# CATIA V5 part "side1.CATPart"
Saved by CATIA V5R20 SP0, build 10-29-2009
Part number: side1
Bounding box of the stored display mesh (mm): x 0 to 18, y 176.777 to 536.776, z -255.116 to 255.116
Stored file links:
  C:\Users\Dell\Desktop\Documentations\week8 doc\side1.CATPart
  C:\Users\Dell\Desktop\Documentations\week8 doc\Part1.CATPart
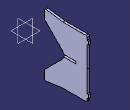
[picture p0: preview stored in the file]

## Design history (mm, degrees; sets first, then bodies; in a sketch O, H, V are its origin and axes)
Body1 (main body)
  DatumCurve1 to DatumCurve6
  DatumSurface1
  DatumCurve7
  DatumSurface2
  Sketch1 on yz-plane, origin (0, 0, 0), H (0, 1, 0), V (0, 0, 1)
    construction line L1 through (0, 141.421) direction (0, 1)
    construction line L2 through (0, 0) direction (1, 0)
    construction line L3 (0, 176.7765) -> (474.2497, 176.7765)
    point P1 (0, 176.7765)
    point P2 (474.2497, 176.7765)
    point P3 (70.8142, 0)
    point P4 (76.4276, 5.6156)
    line L4 (176.7765, 180.9186) -> (176.7765, 245.2199)
    point P5 (176.7765, 176.7765)
    point P6 (176.7765, 256.7765)
    line L5 (179.7054, 173.8476) -> (318.1319, 35.4211)
    arc A1 centre (282.7765, 0.0658) radius 50 from (331.9719, 9) to (318.1319, 35.4211) ccw
    point P7 (318.1319, 35.4211)
    line L6 (188.2132, 255.1162) -> (326.7765, 235)
    point P9 (326.7765, 235)
    point P10 (0, 332.8427)
    point P11 (673.0932, 332.8427)
    line L7 (326.7765, 235) -> (516.7765, 235)
    point P12 (526.7765, 235)
    line L8 (526.7765, 225) -> (526.7765, 205)
    point P13 (526.7765, 0)
    point P14 (332.7765, 0)
    line L9 (526.7765, 205) -> (536.7765, 205)
    point P15 (526.7765, 205)
    point P16 (536.7765, 205)
    line L10 (536.7765, 205) -> (536.7765, 175)
    point P17 (536.7765, 175)
    line L11 (536.7765, 175) -> (526.7765, 175)
    line L12 (526.7765, 175) -> (526.7765, 0)
    point P18 (526.7765, 175)
    line L13 (331.9719, 9) -> (432.7765, 9)
    point P19 (331.9719, 9)
    point P20 (432.7765, 9)
    line L14 (432.7765, 9) -> (432.7765, 0)
    point P21 (432.7765, 0)
    point P22 (0, 0)
    construction line L15 through (0, 0) direction (1, 0)
    construction line L16 through (0, 0) direction (0, -1)
    point P23 (474.2497, -176.7765)
    point P24 (0, -176.7765)
    construction line L17 (0, -176.7765) -> (474.2497, -176.7765)
    point P25 (70.8142, 0)
    point P26 (76.4276, -5.6156)
    point P27 (318.1319, -35.4211)
    point P29 (326.7765, -235)
    point P30 (673.0932, -332.8427)
    point P31 (0, -332.8427)
    construction line L18 (0, -332.8427) -> (673.0932, -332.8427)
    point P32 (526.7765, 0)
    point P33 (332.7765, 0)
    point P34 (526.7765, -205)
    point P35 (536.7765, -205)
    point P36 (536.7765, -175)
    point P37 (526.7765, -175)
    point P38 (331.9719, -9)
    point P39 (432.7765, -9)
    point P40 (432.7765, 0)
    line L19 (176.7765, -180.9186) -> (176.7765, -245.2199)
    line L20 (179.7054, -173.8476) -> (318.1319, -35.4211)
    arc A2 centre (282.7765, -0.0658) radius 50 from (331.9719, -9) to (318.1319, -35.4211) cw
    line L21 (188.2132, -255.1162) -> (326.7765, -235)
    line L22 (326.7765, -235) -> (516.7765, -235)
    line L23 (526.7765, -225) -> (526.7765, -205)
    line L24 (526.7765, -205) -> (536.7765, -205)
    line L25 (536.7765, -205) -> (536.7765, -175)
    line L26 (536.7765, -175) -> (526.7765, -175)
    line L27 (526.7765, -175) -> (526.7765, 0)
    line L28 (331.9719, -9) -> (432.7765, -9)
    line L29 (432.7765, -9) -> (432.7765, 0)
    construction line L30 (0, 474.8557) -> (0, -436.5473)
    point P41 (0, 474.8557)
    arc A3 centre (186.7765, 245.2199) radius 10 from (188.2132, 255.1162) to (176.7765, 245.2199) ccw
    point P43 (188.2132, 255.1162)
    point P44 (176.7765, 245.2199)
    arc A4 centre (516.7765, 225) radius 10 from (516.7765, 235) to (526.7765, 225) cw
    point P46 (516.7765, 235)
    point P47 (526.7765, 225)
    arc A5 centre (186.7765, 180.9186) radius 10 from (176.7765, 180.9186) to (179.7054, 173.8476) ccw
    point P49 (176.7765, 180.9186)
    point P50 (179.7054, 173.8476)
    point P52 (179.7054, -173.8476)
    point P53 (176.7765, -180.9186)
    arc A6 centre (186.7765, -180.9186) radius 10 from (176.7765, -180.9186) to (179.7054, -173.8476) cw
    point P55 (176.7765, -245.2199)
    point P56 (188.2132, -255.1162)
    arc A7 centre (186.7765, -245.2199) radius 10 from (188.2132, -255.1162) to (176.7765, -245.2199) cw
    point P58 (526.7765, -225)
    point P59 (516.7765, -235)
    arc A8 centre (516.7765, -225) radius 10 from (516.7765, -235) to (526.7765, -225) ccw
    distance L3 L2 = 176.7765
    distance P5 L1 = 176.7765
    radius A1 = 50
    distance L4 L8 = 350
    length L9 = 10
    length L10 = 30
    length L14 = 9
    distance P14 L14 = 100
    distance L11 L26 = 350
    distance P5 P6 = 80
    radius A3 = 10
    distance P9 P12 = 200
    distance P12 P15 = 30
    radius A4 = 10
    radius A5 = 10
    distance L29 L27 = 94
    coincidence: P1 L1, L2 H, L2 P3, L1 V, P5 L3, P10 L1, P13 L2, P14 A1, L8 L12, P21 L2, P13 P32, P21 P40, P41 L1, L6 P6, L4 P6, L7 P12, L8 P12, L4 P5, L5 P5
    horizontal: L3 H, L7 H, L9 H, L11 H, L13 H
    vertical: L4 V, L8 V, L10 V, L12 V, L14 V, L30 V
    tangency: A1 L5, A3 L6, A3 L4, A4 L7, A4 L8, A5 L4, A5 L5
    symmetry: O P22 L2, H L15 L2, V L16 L2, P2 P23 L2, P1 P24 L2, L3 L17 L2, P3 P25 L2, P4 P26 L2, P7 P27 L2, P9 P29 L2, P11 P30 L2, P10 P31 L2, P13 P32 L2, P14 P33 L2, P15 P34 L2, P16 P35 L2, P17 P36 L2, P18 P37 L2, P19 P38 L2, P20 P39 L2, P21 P40 L2, L4 L19 L2, L5 L20 L2, A1 A2 L2, L6 L21 L2, L7 L22 L2, L8 L23 L2, L9 L24 L2, L10 L25 L2, L11 L26 L2, L12 L27 L2, L13 L28 L2, L14 L29 L2, P50 P52 L15, P49 P53 L15, A5 A6 L15, P44 P55 L15, P43 P56 L15, A3 A7 L15, P47 P58 L15, P46 P59 L15, A4 A8 L15
  Pad1: profile Sketch1, direction (1, 0, 0), length 18
  DatumSurface3
  DatumSurface4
